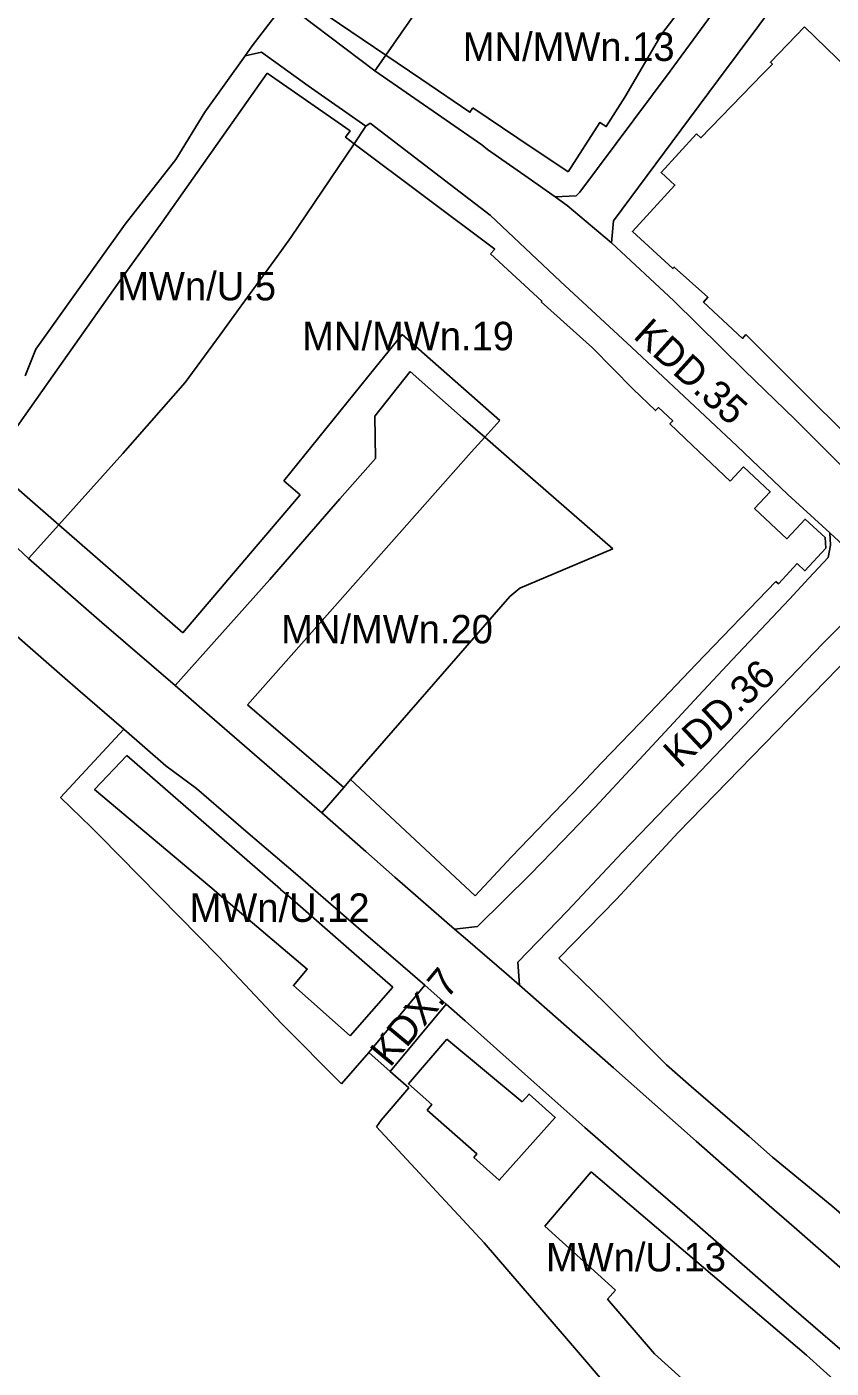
# Model space of a CAD drawing. Extents: x 7425067 to 7426806, y 5549054 to 5550619.
# Drawn here: x 7426205.4 to 7426346.6, y 5549247.2 to 5549482.5 of the extents above; entities that cross this region are included whole.
import ezdxf

# ---------------------------------------------------------------- set-up
doc = ezdxf.new("R2010")
doc.units = 0
for name, color, linetype in [('LIN_Linia Zabudowy Nieprzekraczalna', 7, 'Continuous'), ('LIN_linie_rozgraniczajace', 7, 'Continuous'), ('TXT_Oznaczenia_przeznaczen', 7, 'Continuous')]:
    doc.layers.add(name, color=color, linetype=linetype)

msp = doc.modelspace()

# ---------------------------------------------------------------- linework, layer by layer
at = {"layer": 'LIN_Linia Zabudowy Nieprzekraczalna'}
for points in [[(7426316.82, 5549481.26), (7426332.57, 5549501.84), (7426336.7731, 5549507.332), (7426337.76, 5549506.6)], [(7426256.1733, 5549485.865), (7426268.433, 5549477.5449), (7426274.57, 5549473.38), (7426283.19, 5549467.53), (7426283.6963, 5549468.2744)], [(7426300.42, 5549457.1), (7426305.98, 5549465.73), (7426307.09, 5549465), (7426310.37, 5549470.15), (7426316.82, 5549481.26)], [(7426341.89, 5549482.48), (7426335.9, 5549476.31), (7426336.24, 5549475.98), (7426334.51, 5549474.2), (7426323.6688, 5549463.0455), (7426322.91, 5549463.74)], [(7426359.7724, 5549464.1559), (7426354.45, 5549469.35), (7426352.79, 5549470.97), (7426353.26, 5549471.45), (7426341.89, 5549482.48)], [(7426247.6304, 5549474.4023), (7426229.17, 5549448.23), (7426222.04, 5549438.34), (7426211.11, 5549422.85), (7426198.9753, 5549405.6527)], [(7426286.8, 5549442.72), (7426287.5433, 5549443.508), (7426262.8656, 5549462.0065), (7426261.3666, 5549463.1301), (7426262.15, 5549464.25), (7426247.6304, 5549474.4023)], [(7426283.6963, 5549468.2744), (7426291.59, 5549463), (7426300.42, 5549457.1)], [(7426322.91, 5549463.74), (7426316.71, 5549456.98), (7426319.13, 5549454.76), (7426311.68, 5549446.63), (7426318.79, 5549440.11), (7426319.03, 5549440.37), (7426324.9406, 5549435.0894), (7426324.14, 5549434.23), (7426330.98, 5549427.86), (7426331.6023, 5549428.5271)], [(7426328.8186, 5549402.8067), (7426322.23, 5549409.08), (7426318.26, 5549412.86), (7426318.75, 5549413.37), (7426316.27, 5549415.72), (7426315.76, 5549415.19), (7426311.82, 5549418.94), (7426304.68, 5549426.18), (7426295.7, 5549434.3), (7426295.7982, 5549434.4017), (7426286.8, 5549442.72)], [(7426250.5226, 5549402.8712), (7426266.51, 5549422.63), (7426271.2941, 5549428.5426)], [(7426271.2941, 5549428.5426), (7426288.4516, 5549413.481)], [(7426331.6023, 5549428.5271), (7426359.43, 5549400.79), (7426358.89, 5549400.25), (7426362.88, 5549396.28), (7426363.45, 5549396.86), (7426368.41, 5549391.92), (7426374.46, 5549386.85), (7426387.42, 5549373.83), (7426394.89, 5549366.23), (7426409.06, 5549352.23), (7426417.45, 5549344.27), (7426425.33, 5549336.34)], [(7426288.4516, 5549413.481), (7426285.7783, 5549410.5052), (7426283.42, 5549407.88), (7426244.13, 5549363.57)], [(7426198.9753, 5549405.6527), (7426211.0357, 5549395.1516), (7426227.84, 5549380.52), (7426232.79, 5549376.21)], [(7426340.61, 5549388.36), (7426341.94, 5549387.11), (7426345.64, 5549391.09), (7426345.5, 5549392.94), (7426342.01, 5549396.14), (7426338.76, 5549392.72), (7426333.11, 5549398), (7426335.86, 5549400.94), (7426331.17, 5549405.32), (7426328.8186, 5549402.8067)], [(7426253.4052, 5549400.4121), (7426250.5226, 5549402.8712)], [(7426232.79, 5549376.21), (7426243.71, 5549389.03), (7426253.4052, 5549400.4121)], [(7426336.8274, 5549385.2439), (7426337.29, 5549384.81), (7426340.61, 5549388.36)], [(7426284.0704, 5549330.053), (7426290.4754, 5549336.8978), (7426302.5608, 5549349.4838), (7426306.3401, 5549353.4632), (7426314.6666, 5549362.1399), (7426322.8583, 5549370.7117), (7426336.8274, 5549385.2439)], [(7426356.3766, 5549378.8485), (7426319.69, 5549341.18), (7426308.92, 5549329.51), (7426298.8, 5549319.16)], [(7426244.13, 5549363.57), (7426261.0489, 5549349.0938)], [(7426222.9831, 5549354.7172), (7426217.329, 5549348.7346), (7426237.53, 5549331.69), (7426242.33, 5549327.64), (7426254.6527, 5549317.2427), (7426252.225, 5549314.3279), (7426262.1748, 5549305.512)], [(7426249.9173, 5549331.2373), (7426222.9831, 5549354.7172)], [(7426262.2345, 5549350.4617), (7426261.0489, 5549349.0938)], [(7426262.2345, 5549350.4617), (7426284.0704, 5549330.053)], [(7426269.6755, 5549314.0323), (7426262.4178, 5549320.3668), (7426251.5579, 5549329.8181), (7426249.9387, 5549331.2187), (7426249.9173, 5549331.2373)], [(7426298.8, 5549319.16), (7426306.9, 5549311.25), (7426317.69, 5549300.43), (7426321.98, 5549296.63), (7426332.19, 5549287.84), (7426336.25, 5549284.23)], [(7426262.1748, 5549305.512), (7426262.1965, 5549305.5367), (7426269.6755, 5549314.0323)], [(7426279.1305, 5549304.9266), (7426272.41, 5549297.13), (7426276.48, 5549293.46), (7426275.7, 5549292.51), (7426284.37, 5549284.83), (7426283.8378, 5549284.187)], [(7426292.32, 5549293.94), (7426279.1305, 5549304.9266)], [(7426283.8378, 5549284.187), (7426288.3235, 5549280.1835), (7426298.1559, 5549291.2002), (7426293.5464, 5549295.3141), (7426292.32, 5549293.94)], [(7426336.25, 5549284.23), (7426346.65, 5549275.68), (7426361.6902, 5549262.7143)], [(7426304.43, 5549281.67), (7426299.99, 5549276.45), (7426296.3307, 5549272.1479)], [(7426342.23, 5549249.5), (7426313.15, 5549274.26), (7426304.43, 5549281.67)], [(7426296.3307, 5549272.1479), (7426308.7359, 5549260.9235)], [(7426308.7359, 5549260.9235), (7426307.3308, 5549259.3369), (7426315.5649, 5549249.7426), (7426330.51, 5549236.22), (7426339.23, 5549228.33)], [(7426339.23, 5549228.33), (7426343.8, 5549233.39), (7426344.85, 5549232.44), (7426347.68, 5549235.57), (7426346.68, 5549236.47), (7426351.16, 5549241.43), (7426342.23, 5549249.5)]]:
    msp.add_lwpolyline(points, dxfattribs=at)
at = {"layer": 'LIN_linie_rozgraniczajace'}
for points in [[(7426266.52, 5549474.7853), (7426268.433, 5549477.5449), (7426279.59, 5549493.64)], [(7426327.68, 5549487.52), (7426318.3, 5549474.76)], [(7426337.31, 5549487.4), (7426326.8, 5549473.28)], [(7426244.99, 5549479.2), (7426250.22, 5549486.01)], [(7426253.35, 5549484.75), (7426266.52, 5549474.7853)], [(7426236.67, 5549467.54), (7426243.727, 5549477.43), (7426244.99, 5549479.2)], [(7426243.727, 5549477.43), (7426246.6111, 5549478.0423)], [(7426246.6111, 5549478.0423), (7426254.82, 5549472.18)], [(7426266.52, 5549474.7853), (7426285.2601, 5549461.8299)], [(7426318.3, 5549474.76), (7426302.49, 5549453.52)], [(7426326.8, 5549473.28), (7426321.69, 5549466.43)], [(7426254.82, 5549472.18), (7426264.92, 5549465.06)], [(7426231.58, 5549459.21), (7426236.67, 5549467.54)], [(7426321.69, 5549466.43), (7426308.3434, 5549448.476)], [(7426251.78, 5549445.53), (7426262.8656, 5549462.0065), (7426264.92, 5549465.06)], [(7426264.92, 5549465.06), (7426265.69, 5549465.62)], [(7426265.69, 5549465.62), (7426286.74, 5549449.45)], [(7426285.2601, 5549461.8299), (7426286.2641, 5549461.0103)], [(7426222.68, 5549447.89), (7426231.58, 5549459.21)], [(7426286.2641, 5549461.0103), (7426293.39, 5549456.01)], [(7426293.39, 5549456.01), (7426298.1264, 5549452.6821)], [(7426301.8401, 5549452.8439), (7426298.1264, 5549452.6821)], [(7426300.25, 5549451.19), (7426298.1264, 5549452.6821)], [(7426302.49, 5549453.52), (7426301.8401, 5549452.8439)], [(7426308.036, 5549444.6391), (7426300.25, 5549451.19)], [(7426213.25, 5549434.74), (7426222.68, 5549447.89)], [(7426286.74, 5549449.45), (7426299.09, 5549437.81)], [(7426308.3434, 5549448.476), (7426308.036, 5549444.6391)], [(7426249.37, 5549442.22), (7426251.78, 5549445.53)], [(7426308.036, 5549444.6391), (7426318.93, 5549434.46)], [(7426244.18, 5549435.11), (7426249.37, 5549442.22)], [(7426299.09, 5549437.81), (7426311.52, 5549426.3)], [(7426208.75, 5549428.445), (7426213.25, 5549434.74)], [(7426239.34, 5549428.49), (7426243.04, 5549433.56)], [(7426243.04, 5549433.56), (7426244.18, 5549435.11)], [(7426318.93, 5549434.46), (7426331.34, 5549422.22)], [(7426206.994, 5549425.9885), (7426208.75, 5549428.445)], [(7426233.24, 5549420.13), (7426239.34, 5549428.49)], [(7426311.52, 5549426.3), (7426329.98, 5549409.03)], [(7426205.15, 5549421.27), (7426206.994, 5549425.9885)], [(7426272.69, 5549422.04), (7426266.49, 5549414.2)], [(7426281.97, 5549413.82), (7426272.69, 5549422.04)], [(7426331.34, 5549422.22), (7426340.24, 5549413.65)], [(7426222.3, 5549407.66), (7426233.24, 5549420.13)], [(7426266.49, 5549414.2), (7426266.6, 5549406.77)], [(7426281.97, 5549413.82), (7426285.7783, 5549410.5052), (7426291.54, 5549405.49)], [(7426340.24, 5549413.65), (7426349.88, 5549404)], [(7426205.73, 5549389.26), (7426211.0357, 5549395.1516), (7426222.3, 5549407.66)], [(7426329.98, 5549409.03), (7426338.94, 5549400.45)], [(7426266.6, 5549406.77), (7426260.38, 5549399.72)], [(7426291.54, 5549405.49), (7426308.24, 5549390.93)], [(7426338.94, 5549400.45), (7426346.33, 5549393.77)], [(7426196.44, 5549397.9), (7426205.73, 5549389.26)], [(7426260.38, 5549399.72), (7426248.09, 5549385.59)], [(7426346.33, 5549393.77), (7426346.42, 5549391.56)], [(7426346.33, 5549393.77), (7426355.73, 5549385.06)], [(7426291.9171, 5549384.0636), (7426308.24, 5549390.93)], [(7426346.42, 5549391.56), (7426346.05, 5549389.42)], [(7426205.73, 5549389.26), (7426218.62, 5549378.01)], [(7426346.05, 5549389.42), (7426342.645, 5549385.78)], [(7426248.09, 5549385.59), (7426231.48, 5549366.95)], [(7426290.154, 5549382.5622), (7426291.9171, 5549384.0636)], [(7426342.645, 5549385.78), (7426339.24, 5549382.14)], [(7426257.18, 5549344.63), (7426261.0489, 5549349.0938), (7426262.2345, 5549350.4617), (7426290.154, 5549382.5622)], [(7426339.24, 5549382.14), (7426334.2, 5549376.795)], [(7426353.6206, 5549382.9247), (7426345.17, 5549374.37)], [(7426212.1, 5549368.28), (7426202.28, 5549376.85)], [(7426218.62, 5549378.01), (7426231.48, 5549366.95)], [(7426334.2, 5549376.795), (7426329.16, 5549371.45)], [(7426334.85, 5549363.68), (7426345.17, 5549374.37)], [(7426329.16, 5549371.45), (7426323.295, 5549365.15)], [(7426214.41, 5549366.26), (7426212.1, 5549368.28)], [(7426222.44, 5549359.29), (7426214.41, 5549366.26)], [(7426231.48, 5549366.95), (7426236.64, 5549362.49)], [(7426323.295, 5549365.15), (7426317.43, 5549358.85)], [(7426322.4, 5549350.65), (7426334.85, 5549363.68)], [(7426236.64, 5549362.49), (7426257.18, 5549344.63)], [(7426211.33, 5549347.32), (7426222.44, 5549359.29)], [(7426222.44, 5549359.29), (7426226.145, 5549356.08)], [(7426317.43, 5549358.85), (7426311.275, 5549352.225)], [(7426226.145, 5549356.08), (7426229.85, 5549352.87)], [(7426229.85, 5549352.87), (7426235.21, 5549348.91)], [(7426311.275, 5549352.225), (7426305.12, 5549345.6)], [(7426235.21, 5549348.91), (7426243.88, 5549341.445)], [(7426316.16, 5549344.195), (7426322.4, 5549350.65)], [(7426216.81, 5549342.06), (7426211.33, 5549347.32)], [(7426257.18, 5549344.63), (7426264.93, 5549337.84)], [(7426305.12, 5549345.6), (7426299.465, 5549339.745)], [(7426309.92, 5549337.74), (7426316.16, 5549344.195)], [(7426218.25, 5549340.59), (7426216.81, 5549342.06)], [(7426243.88, 5549341.445), (7426252.55, 5549333.98)], [(7426239.06, 5549319.44), (7426218.25, 5549340.59)], [(7426299.465, 5549339.745), (7426293.81, 5549333.89)], [(7426264.93, 5549337.84), (7426270.02, 5549333.38)], [(7426300.26, 5549327.4), (7426309.92, 5549337.74)], [(7426252.55, 5549333.98), (7426258.75, 5549328.62)], [(7426270.02, 5549333.38), (7426280.4798, 5549324.2267), (7426282.3735, 5549322.5695)], [(7426293.81, 5549333.89), (7426284.5155, 5549324.6861)], [(7426258.75, 5549328.62), (7426264.95, 5549323.26)], [(7426291.6, 5549318.46), (7426300.26, 5549327.4)], [(7426264.95, 5549323.26), (7426270.12, 5549318.845)], [(7426284.5155, 5549324.6861), (7426280.4798, 5549324.2267)], [(7426282.3735, 5549322.5695), (7426289.62, 5549316.41)], [(7426250.1, 5549307.66), (7426239.06, 5549319.44)], [(7426270.12, 5549318.845), (7426275.29, 5549314.43)], [(7426291.6, 5549318.46), (7426291.8744, 5549314.4258)], [(7426289.62, 5549316.41), (7426291.8744, 5549314.4258), (7426308.39, 5549299.89)], [(7426265.45, 5549302.61), (7426275.29, 5549314.43)], [(7426275.29, 5549314.43), (7426279.0259, 5549311.1027), (7426282.33, 5549308.16)], [(7426269.1941, 5549299.2926), (7426279.0259, 5549311.1027)], [(7426260.63, 5549297.12), (7426250.1, 5549307.66)], [(7426282.33, 5549308.16), (7426292.82, 5549298.8)], [(7426265.45, 5549302.61), (7426260.63, 5549297.12)], [(7426272.47, 5549296.39), (7426269.1941, 5549299.2926), (7426265.45, 5549302.61)], [(7426308.39, 5549299.89), (7426322.88, 5549287.03)], [(7426292.82, 5549298.8), (7426303.31, 5549289.44)], [(7426267.59, 5549290.74), (7426272.47, 5549296.39)], [(7426266.76, 5549289.58), (7426267.59, 5549290.74)], [(7426285.69, 5549269.19), (7426266.76, 5549289.58)], [(7426303.31, 5549289.44), (7426312.08, 5549281.86)], [(7426322.88, 5549287.03), (7426335.7, 5549275.74)], [(7426312.08, 5549281.86), (7426320.85, 5549274.28)], [(7426335.7, 5549275.74), (7426340.05, 5549271.94)], [(7426320.85, 5549274.28), (7426330.005, 5549266.275)], [(7426340.05, 5549271.94), (7426354.14, 5549259.61)], [(7426300.45, 5549252), (7426285.69, 5549269.19)], [(7426330.005, 5549266.275), (7426339.16, 5549258.27)], [(7426339.16, 5549258.27), (7426349.305, 5549249.565)], [(7426316.85, 5549232.89), (7426300.45, 5549252)]]:
    msp.add_lwpolyline(points, dxfattribs=at)

# ---------------------------------------------------------------- texts
at = {"layer": 'TXT_Oznaczenia_przeznaczen'}
for s, p in [('MN/MWn.13', (7426281.9324, 5549476.5248)), ('MWn/U.5', (7426221.3008, 5549434.5298)), ('MN/MWn.19', (7426253.755, 5549425.7695)), ('MN/MWn.20', (7426250.0584, 5549374.3507)), ('MWn/U.12', (7426233.9948, 5549325.5048)), ('MWn/U.13', (7426296.5252, 5549264.2005))]:
    msp.add_text(s, height=5, dxfattribs=at).set_placement(p)
for s, rotation, p in [('KDD.35', 317.868166, (7426311.6304, 5549428.0553)), ('KDD.36', 43.092883, (7426320.028, 5549352.2874)), ('KDX.7', 50.187556, (7426269.15, 5549299.8521))]:
    msp.add_text(s, height=5, rotation=rotation, dxfattribs=at).set_placement(p)

doc.saveas('drawing.dxf')
